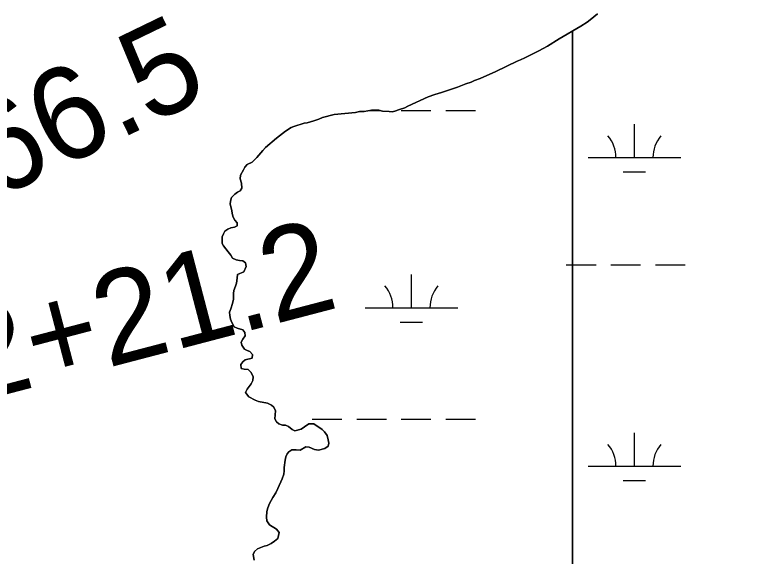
# Model space of a CAD drawing. Extents: x 3192927 to 3230760, y 831141 to 856475.
# Drawn here: x 3199405 to 3200202, y 844300 to 844884 of the extents above; entities that cross this region are included whole.
import ezdxf

# ---------------------------------------------------------------- set-up
doc = ezdxf.new("R2010")
doc.units = 0
for name, color, linetype in [('V-SITE-VEGE', 7, 'Continuous'), ('V-SURV-IDEN', 7, 'Continuous'), ('V-TOPO-SHOR', 7, 'Continuous'), ('V-WETL-SWMP', 7, 'Continuous')]:
    doc.layers.add(name, color=color, linetype=linetype)

msp = doc.modelspace()

# ---------------------------------------------------------------- linework, layer by layer
at = {"layer": 'V-SITE-VEGE'}
for points in [[(3200033.17, 844885.18), (3200025, 844878.54), (3200021.81, 844876.27), (3200015.06, 844871.93)], [(3200015.06, 844871.93), (3199991.86, 844858.02), (3199979.16, 844850.11), (3199969.65, 844845.06), (3199954.62, 844837.59), (3199949.87, 844835.56), (3199946.33, 844834.27), (3199923.57, 844822.89), (3199906.58, 844815.47), (3199900.46, 844813.08), (3199896.71, 844811.41), (3199890.99, 844809.59), (3199881.91, 844805.9), (3199864.97, 844800.24), (3199857.68, 844798.07), (3199850.58, 844795.5), (3199828.44, 844785.47), (3199825.28, 844783.79), (3199819.56, 844781.97), (3199814.63, 844780.13), (3199811.49, 844779.62), (3199808.37, 844779.69), (3199801.34, 844780.25), (3199797.06, 844781.14), (3199792.57, 844781.24), (3199789.24, 844781.12), (3199781.39, 844779.94), (3199776.3, 844779.68), (3199771.98, 844778.8), (3199749.05, 844776.41), (3199736.46, 844773.39), (3199732.52, 844771.72), (3199727.19, 844769.9), (3199719.91, 844767.72), (3199716.57, 844767.22), (3199705.54, 844763.76), (3199702.58, 844762.47), (3199696.62, 844758.51), (3199686.86, 844751.11), (3199674.89, 844740.84), (3199672.08, 844737.78), (3199665.64, 844730.11), (3199660.44, 844725.15), (3199655.29, 844722.54), (3199652.8, 844719.93), (3199651.28, 844716.88), (3199648.06, 844711.19), (3199647.76, 844707.29), (3199649.09, 844702.72), (3199649.58, 844697.15), (3199647.65, 844694.11), (3199644.94, 844692.73), (3199641.8, 844690.75), (3199638.41, 844686.92), (3199637.29, 844683.03), (3199636.8, 844679.95), (3199638.7, 844673.11), (3199639.03, 844669.81), (3199640.17, 844665.87), (3199641.95, 844662.74), (3199644.56, 844659.79), (3199644.27, 844656.5), (3199641.56, 844655.13), (3199637.63, 844654.4), (3199634.51, 844653.03), (3199631.15, 844650.64), (3199629.65, 844648), (3199628.13, 844644.74), (3199628.37, 844637.53), (3199629.75, 844634.82), (3199634.54, 844628.52), (3199637.54, 844624.95), (3199639.32, 844621.82), (3199643.39, 844619.87), (3199646.88, 844619.17), (3199650.57, 844618.87), (3199653.4, 844616.54), (3199654.14, 844612.81), (3199651.73, 844606.9), (3199644.86, 844603.97), (3199644.56, 844600.07), (3199643.81, 844594.73), (3199642.5, 844591.47), (3199640.95, 844586.97), (3199640.45, 844583.49), (3199640.31, 844577.31), (3199639.38, 844572.8), (3199637.58, 844566.87), (3199636.27, 844563.61), (3199636.39, 844559.9), (3199637.32, 844555.97), (3199638.67, 844552.23), (3199641.03, 844547.64), (3199644.29, 844546.12), (3199650.64, 844544.32), (3199652.63, 844541.59), (3199653.16, 844538.08), (3199650.6, 844534.23), (3199648.88, 844531.18), (3199649.41, 844527.87), (3199652.4, 844523.68)], [(3199652.4, 844523.68), (3199655.04, 844521.97), (3199658.1, 844520.87), (3199660.91, 844517.71), (3199660.41, 844514.02), (3199652.95, 844512.14), (3199650.42, 844509.93), (3199648.3, 844507.1), (3199648.81, 844502.76), (3199652.08, 844501.86), (3199656.2, 844501.76), (3199659.42, 844498.39), (3199661.77, 844493.6), (3199661.27, 844489.9), (3199659.33, 844486.24), (3199655.07, 844480.58), (3199653.54, 844476.7), (3199656.93, 844472.3), (3199663.85, 844468.63), (3199667.52, 844467.3), (3199676.95, 844465.22), (3199681.42, 844463.05), (3199684.06, 844461.14), (3199685.61, 844457.19), (3199685.19, 844448.34), (3199686.97, 844445.21), (3199689.39, 844443.09), (3199693.26, 844441.56), (3199696.56, 844441.48), (3199699.62, 844440.17), (3199703.65, 844436.78), (3199706.71, 844435.47), (3199713.34, 844437.37), (3199717.11, 844439.75), (3199721.72, 844442.94), (3199727.28, 844443.01), (3199735.99, 844437.03), (3199738.61, 844434.5), (3199741.6, 844430.51), (3199742.72, 844425.75), (3199743.25, 844422.23), (3199742.56, 844418.96), (3199738.99, 844416.36), (3199732.16, 844414.67), (3199727.85, 844415.4), (3199721.94, 844417.8), (3199718.45, 844418.3), (3199712.38, 844414.53), (3199707.86, 844415.05), (3199703.34, 844415.16), (3199700.19, 844412.97), (3199698.28, 844410.55), (3199696.98, 844407.49), (3199696.27, 844404), (3199695.26, 844396), (3199695.17, 844392.29), (3199694.67, 844388.6), (3199692.9, 844383.7), (3199688.33, 844373.31), (3199685.95, 844368.63), (3199682.74, 844363.55), (3199679.29, 844357.25), (3199677.32, 844352.56), (3199676.4, 844348.47), (3199676.05, 844342.51), (3199676.57, 844338.37), (3199679.35, 844333.98), (3199686.86, 844329.47), (3199689.86, 844325.7), (3199688.27, 844319.35), (3199684.7, 844316.55), (3199680.93, 844314.18), (3199676.76, 844311.8), (3199673.65, 844311.05), (3199666.17, 844308.14), (3199663.01, 844305.54), (3199661.49, 844302.08), (3199662.58, 844295.87)]]:
    msp.add_lwpolyline(points, dxfattribs=at)
at = {"layer": 'V-TOPO-SHOR'}
for points in [[(3199652.8, 844719.93), (3199655.29, 844722.54), (3199660.44, 844725.15), (3199665.64, 844730.11), (3199672.08, 844737.78), (3199674.89, 844740.84), (3199686.86, 844751.11), (3199696.62, 844758.51), (3199702.58, 844762.47), (3199705.54, 844763.76), (3199716.57, 844767.22), (3199719.91, 844767.72), (3199727.19, 844769.9), (3199732.52, 844771.72), (3199736.46, 844773.39), (3199749.05, 844776.41), (3199771.98, 844778.8), (3199776.3, 844779.68), (3199781.39, 844779.94), (3199789.24, 844781.12), (3199792.57, 844781.24), (3199797.06, 844781.13), (3199801.34, 844780.25), (3199808.37, 844779.69), (3199811.49, 844779.62), (3199814.63, 844780.13), (3199819.56, 844781.97), (3199825.28, 844783.79), (3199828.44, 844785.47), (3199850.58, 844795.5), (3199857.68, 844798.07), (3199864.97, 844800.24), (3199881.91, 844805.9), (3199890.99, 844809.59), (3199896.71, 844811.41), (3199900.46, 844813.08), (3199906.58, 844815.47), (3199923.57, 844822.89), (3199946.33, 844834.27), (3199949.87, 844835.56), (3199954.62, 844837.59), (3199969.65, 844845.06), (3199979.16, 844850.11), (3199991.86, 844858.02), (3200015.06, 844871.93), (3200021.81, 844876.27), (3200025, 844878.54), (3200033.17, 844885.18)], [(3199676.95, 844465.22), (3199667.52, 844467.3), (3199663.85, 844468.63), (3199656.93, 844472.3), (3199653.54, 844476.7), (3199655.07, 844480.58), (3199659.33, 844486.24), (3199661.27, 844489.9), (3199661.77, 844493.6), (3199659.41, 844498.39), (3199656.2, 844501.76), (3199652.08, 844501.86), (3199648.81, 844502.76), (3199648.3, 844507.1), (3199650.42, 844509.93), (3199652.95, 844512.14), (3199660.41, 844514.02), (3199660.91, 844517.71), (3199658.1, 844520.87), (3199655.04, 844521.97), (3199652.4, 844523.68), (3199649.41, 844527.87), (3199648.88, 844531.18), (3199650.6, 844534.23), (3199653.16, 844538.08), (3199652.63, 844541.59), (3199650.64, 844544.32), (3199644.29, 844546.12), (3199641.03, 844547.64), (3199638.67, 844552.23), (3199637.32, 844555.97), (3199636.39, 844559.9), (3199636.27, 844563.61), (3199637.58, 844566.87), (3199639.38, 844572.8), (3199640.31, 844577.31), (3199640.45, 844583.49), (3199640.95, 844586.97), (3199642.5, 844591.47), (3199643.81, 844594.73), (3199644.56, 844600.07), (3199644.86, 844603.97), (3199651.73, 844606.9), (3199654.14, 844612.81), (3199653.4, 844616.54), (3199650.57, 844618.87), (3199646.88, 844619.17), (3199643.39, 844619.87), (3199639.32, 844621.82), (3199637.54, 844624.95), (3199634.54, 844628.52), (3199629.75, 844634.82), (3199628.37, 844637.53), (3199628.13, 844644.74), (3199629.65, 844648), (3199631.15, 844650.64), (3199634.51, 844653.03), (3199637.63, 844654.4), (3199641.56, 844655.13), (3199644.27, 844656.5), (3199644.56, 844659.79), (3199641.95, 844662.74), (3199640.17, 844665.87), (3199639.03, 844669.81), (3199638.7, 844673.11), (3199636.8, 844679.95), (3199637.29, 844683.03), (3199638.41, 844686.92), (3199641.8, 844690.75), (3199644.94, 844692.73), (3199647.65, 844694.11), (3199649.57, 844697.15), (3199649.09, 844702.72), (3199647.76, 844707.29), (3199648.06, 844711.19), (3199651.28, 844716.88), (3199652.8, 844719.93)], [(3199662.58, 844295.87), (3199661.49, 844302.08), (3199663.01, 844305.54), (3199666.17, 844308.14), (3199673.65, 844311.05), (3199676.76, 844311.8), (3199680.93, 844314.17), (3199684.7, 844316.55), (3199688.27, 844319.35), (3199689.86, 844325.7), (3199686.86, 844329.47), (3199679.35, 844333.98), (3199676.57, 844338.37), (3199676.05, 844342.51), (3199676.4, 844348.47), (3199677.32, 844352.56), (3199679.29, 844357.25), (3199682.74, 844363.55), (3199685.95, 844368.63), (3199688.33, 844373.31), (3199692.9, 844383.7), (3199694.67, 844388.6), (3199695.17, 844392.29), (3199695.26, 844396), (3199696.27, 844404), (3199696.98, 844407.49), (3199698.28, 844410.55), (3199700.19, 844412.97), (3199703.34, 844415.16), (3199707.86, 844415.05), (3199712.38, 844414.53), (3199718.45, 844418.3), (3199721.94, 844417.8), (3199727.85, 844415.4), (3199732.16, 844414.67), (3199738.99, 844416.36), (3199742.56, 844418.96), (3199743.25, 844422.23), (3199742.72, 844425.75), (3199741.6, 844430.51), (3199738.61, 844434.5), (3199735.99, 844437.03), (3199727.28, 844443.01), (3199721.72, 844442.94), (3199717.11, 844439.75), (3199713.34, 844437.37), (3199706.71, 844435.47), (3199703.65, 844436.78), (3199699.62, 844440.17), (3199696.56, 844441.48), (3199693.26, 844441.56), (3199689.39, 844443.09), (3199686.97, 844445.21), (3199685.19, 844448.34), (3199685.61, 844457.19), (3199684.06, 844461.14), (3199681.42, 844463.05), (3199676.95, 844465.22)]]:
    msp.add_lwpolyline(points, dxfattribs=at)
at = {"layer": 'V-WETL-SWMP'}
for p, q in [((3199787.19, 844780.82), (3199798.6, 844780.82)), ((3199821.48, 844780.82), (3199853.48, 844780.82)), ((3199869.48, 844780.82), (3199901.48, 844780.82)), ((3200072.9, 844730.08), (3200072.9, 844766.08)), ((3200022.9, 844730.08), (3200122.9, 844730.08)), ((3200060.9, 844714.65), (3200084.9, 844714.65)), ((3199999.39, 844614.64), (3200005.96, 844614.64)), ((3200005.99, 844614.65), (3200031.5, 844614.65)), ((3200047.5, 844614.65), (3200079.5, 844614.65)), ((3200095.5, 844614.65), (3200127.5, 844614.65)), ((3199832.32, 844568.21), (3199832.32, 844604.21)), ((3199782.32, 844568.21), (3199882.32, 844568.21)), ((3199820.32, 844552.78), (3199844.32, 844552.78)), ((3199725.48, 844448.14), (3199757.48, 844448.14)), ((3199773.48, 844448.14), (3199805.48, 844448.14)), ((3199821.48, 844448.14), (3199853.48, 844448.14)), ((3199869.48, 844448.14), (3199901.48, 844448.14)), ((3200072.91, 844397.4), (3200072.91, 844433.4)), ((3200022.91, 844397.4), (3200122.91, 844397.4)), ((3200060.91, 844381.97), (3200084.91, 844381.97))]:
    msp.add_line(p, q, dxfattribs=at)
for points in [[(3200033.17, 844885.18), (3200025, 844878.54), (3200021.81, 844876.27), (3200015.06, 844871.93), (3200005.96, 844866.47), (3200005.96, 843977.71), (3200020.05, 843980.04), (3200080.16, 843963.29), (3200199.55, 843911.33), (3200236.09, 843895.13), (3200256.76, 843888.35), (3200277.48, 843884.32), (3200298.36, 843886.58), (3200313.85, 843893.28), (3200334.97, 843905.74), (3200374.66, 843889.47), (3200465.11, 843860.2), (3200601.51, 843829.84), (3200608.05, 843823.79), (3200615.47, 843805.54)], [(3200005.96, 844866.47), (3199991.86, 844858.02), (3199979.16, 844850.11), (3199969.65, 844845.06), (3199954.62, 844837.59), (3199949.88, 844835.56), (3199946.33, 844834.27), (3199923.57, 844822.89), (3199906.58, 844815.47), (3199900.46, 844813.08), (3199896.71, 844811.41), (3199891, 844809.59), (3199881.91, 844805.9), (3199864.97, 844800.24), (3199857.68, 844798.07), (3199850.58, 844795.5), (3199828.45, 844785.47), (3199825.28, 844783.79), (3199819.56, 844781.97), (3199814.63, 844780.13), (3199811.49, 844779.62), (3199808.37, 844779.69), (3199801.34, 844780.25), (3199797.06, 844781.13), (3199792.57, 844781.24), (3199789.24, 844781.12), (3199781.39, 844779.94), (3199776.3, 844779.67), (3199771.98, 844778.8), (3199749.05, 844776.41), (3199736.46, 844773.39), (3199732.52, 844771.72), (3199727.19, 844769.9), (3199719.91, 844767.72), (3199716.57, 844767.22), (3199705.54, 844763.77), (3199702.58, 844762.47), (3199696.62, 844758.5), (3199686.86, 844751.11), (3199674.89, 844740.84), (3199672.08, 844737.78), (3199665.64, 844730.11), (3199660.44, 844725.15), (3199655.29, 844722.54), (3199652.8, 844719.93), (3199651.28, 844716.88), (3199648.06, 844711.19), (3199647.76, 844707.29), (3199649.09, 844702.72), (3199649.57, 844697.15), (3199647.65, 844694.11), (3199644.94, 844692.73), (3199641.8, 844690.75), (3199638.41, 844686.92), (3199637.29, 844683.03), (3199636.8, 844679.95), (3199638.7, 844673.11), (3199639.03, 844669.81), (3199640.17, 844665.87), (3199641.95, 844662.74), (3199644.56, 844659.79), (3199644.27, 844656.5), (3199641.56, 844655.13), (3199637.63, 844654.4), (3199634.51, 844653.03), (3199631.16, 844650.64), (3199629.65, 844648), (3199628.13, 844644.74), (3199628.37, 844637.53), (3199629.75, 844634.82), (3199634.54, 844628.52), (3199637.54, 844624.95), (3199639.32, 844621.82), (3199643.39, 844619.87), (3199646.87, 844619.17), (3199650.57, 844618.87), (3199653.4, 844616.54), (3199654.14, 844612.81), (3199651.73, 844606.9), (3199644.86, 844603.97), (3199644.56, 844600.07), (3199643.81, 844594.73), (3199642.5, 844591.47), (3199640.95, 844586.97), (3199640.46, 844583.49), (3199640.31, 844577.31), (3199639.37, 844572.8), (3199637.58, 844566.87), (3199636.27, 844563.61), (3199636.39, 844559.9), (3199637.32, 844555.96), (3199638.67, 844552.23), (3199641.03, 844547.64), (3199644.29, 844546.12), (3199650.63, 844544.32), (3199652.63, 844541.59), (3199653.16, 844538.08), (3199650.6, 844534.23), (3199648.88, 844531.18), (3199649.41, 844527.87), (3199652.4, 844523.68)], [(3200005.96, 843977.71), (3200005.96, 844866.47)], [(3199652.4, 844523.68), (3199655.04, 844521.97), (3199658.1, 844520.87), (3199660.91, 844517.71), (3199660.41, 844514.02), (3199652.95, 844512.14), (3199650.42, 844509.93), (3199648.3, 844507.1), (3199648.81, 844502.76), (3199652.08, 844501.86), (3199656.2, 844501.76), (3199659.41, 844498.39), (3199661.77, 844493.59), (3199661.27, 844489.9), (3199659.33, 844486.24), (3199655.07, 844480.58), (3199653.54, 844476.7), (3199656.93, 844472.29), (3199663.85, 844468.63), (3199667.52, 844467.3), (3199676.95, 844465.22), (3199681.42, 844463.06), (3199684.06, 844461.14), (3199685.61, 844457.19), (3199685.19, 844448.34), (3199686.97, 844445.21), (3199689.39, 844443.09), (3199693.26, 844441.56), (3199696.56, 844441.48), (3199699.61, 844440.17), (3199703.65, 844436.78), (3199706.71, 844435.47), (3199713.34, 844437.37), (3199717.11, 844439.75), (3199721.72, 844442.93), (3199727.28, 844443.01), (3199735.99, 844437.03), (3199738.61, 844434.5), (3199741.6, 844430.51), (3199742.72, 844425.75), (3199743.25, 844422.23), (3199742.56, 844418.96), (3199738.99, 844416.36), (3199732.16, 844414.68), (3199727.85, 844415.4), (3199721.94, 844417.8), (3199718.45, 844418.3), (3199712.38, 844414.53), (3199707.87, 844415.05), (3199703.34, 844415.16), (3199700.2, 844412.97), (3199698.28, 844410.55), (3199696.97, 844407.49), (3199696.27, 844404.01), (3199695.26, 844396), (3199695.17, 844392.29), (3199694.67, 844388.6), (3199692.9, 844383.7), (3199688.33, 844373.31), (3199685.95, 844368.63), (3199682.74, 844363.56), (3199679.29, 844357.25), (3199677.32, 844352.56), (3199676.4, 844348.47), (3199676.05, 844342.5), (3199676.57, 844338.37), (3199679.35, 844333.98), (3199686.86, 844329.47), (3199689.86, 844325.7), (3199688.26, 844319.35), (3199684.7, 844316.55), (3199680.93, 844314.17), (3199676.76, 844311.8), (3199673.65, 844311.05), (3199666.17, 844308.14), (3199663.01, 844305.54), (3199661.49, 844302.08), (3199662.58, 844295.87)]]:
    msp.add_lwpolyline(points, dxfattribs=at)
for centre, start, end in [((3200017.66, 844730.55), 359.22818, 40.77184), ((3200128.15, 844730.55), 139.22818, 180.77184), ((3199777.08, 844568.69), 359.22818, 40.77184), ((3199887.57, 844568.69), 139.22818, 180.77184), ((3200017.66, 844397.88), 359.22818, 40.77184), ((3200128.15, 844397.88), 139.22818, 180.77184)]:
    msp.add_arc(centre, 35.25, start, end, dxfattribs=at)

# ---------------------------------------------------------------- texts
at = {"layer": 'V-SURV-IDEN'}
for s, rotation, p in [('1011+66.5', 25.83528, (3199044.64, 844520.42)), ('1012+21.2', 14.65878, (3199141.17, 844408.27))]:
    msp.add_text(s, height=100, rotation=rotation, dxfattribs=at).set_placement(p)

doc.saveas('drawing.dxf')
